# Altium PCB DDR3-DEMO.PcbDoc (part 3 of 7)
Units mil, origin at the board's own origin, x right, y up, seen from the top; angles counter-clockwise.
Board outline 2827 x 2165.35 mil, 8 copper layers (TOP, GND02, ART03, ART04, PWR05, ART06, GND07, BOTTOM); 111 components, 133 nets, 5542 pads, 873 vias.
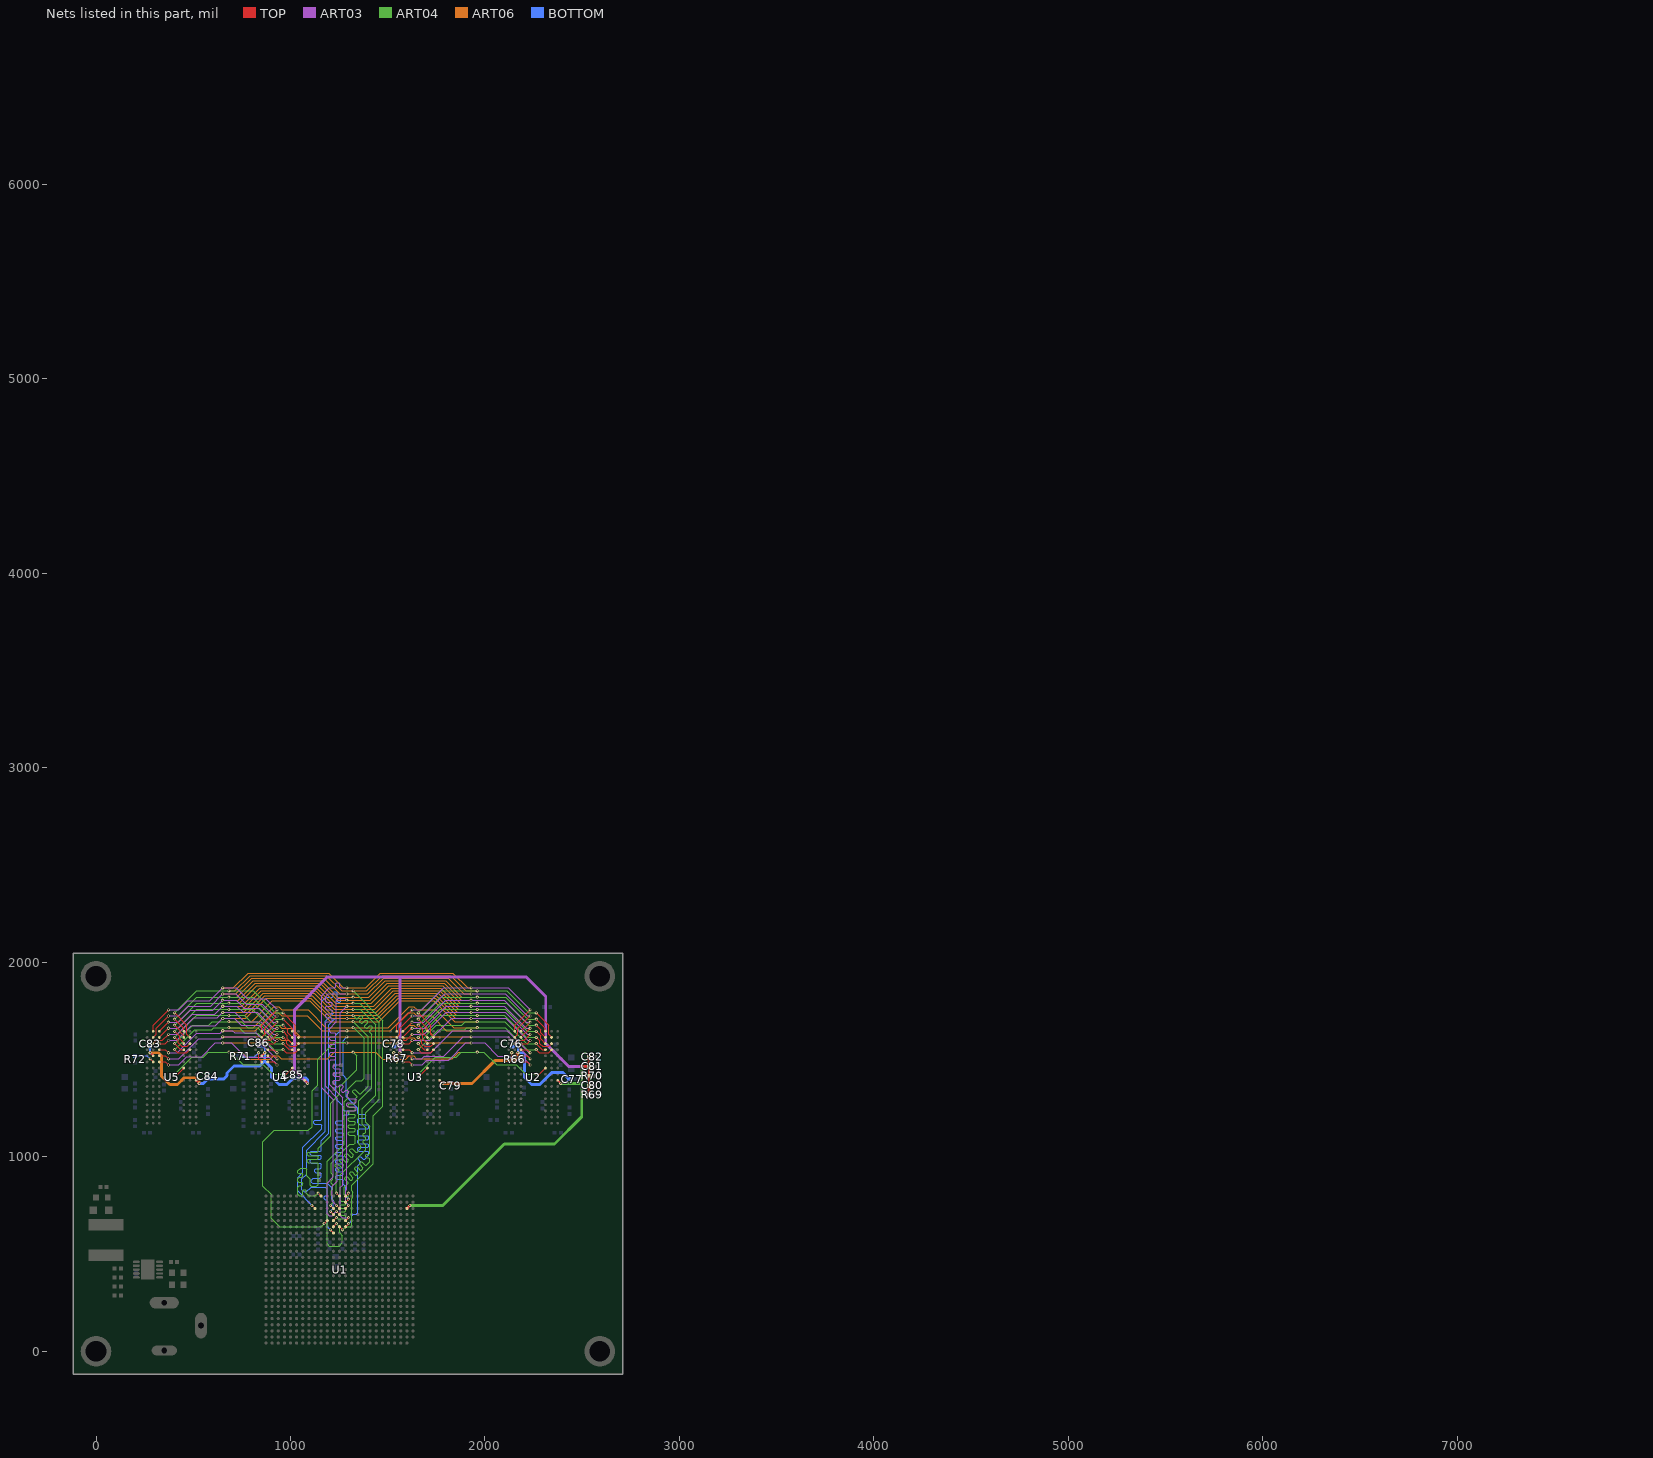
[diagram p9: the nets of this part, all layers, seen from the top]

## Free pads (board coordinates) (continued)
  round 8 on Drill Drawing: 1(4391.24,708.77) 1(4391.24,708.77) 1(4391.24,783.77) 1(4391.24,783.77) 1(4409.9,708.77) 1(4409.9,708.77) 1(4409.9,783.77) 1(4409.9,783.77) 1(4417.37,712.52) 1(4417.37,712.52) 1(4417.37,780.02) 1(4417.37,780.02) 1(4422.97,717.52) 1(4422.97,717.52) 1(4422.97,775.02) 1(4422.97,775.02) 1(4427.64,725.02) 1(4427.64,725.02) 1(4427.64,767.52) 1(4427.64,767.52) 1(4431.37,733.77) 1(4431.37,733.77) 1(4431.37,758.77) 1(4431.37,758.77) 1(4432.3,746.27) 1(4432.3,746.27) 1(4475.58,708.77) 1(4475.58,783.77) 1(4486.78,708.77) 1(4486.78,783.77) 1(4497.97,708.77) 1(4497.97,783.77) 1(4544.05,708.77) 1(4544.05,747.52) 1(4544.05,783.77) 1(4544.05,783.77) 1(4566.45,747.52) 1(4579.51,783.77) 1(4593.44,1542.62) 1(4597.17,1588.88) 1(4597.17,1588.88) 1(4599.04,1597.63) 1(4599.04,1597.63) 1(4599.97,1580.12) 1(4599.97,1580.12) 1(4600.91,1536.38) 1(4600.91,1536.38) 1(4603.71,1603.88) 1(4603.71,1603.88) 1(4606.51,1575.12) 1(4606.51,1575.12) 1(4609.31,1532.62) 1(4609.31,1532.62) 1(4610.24,1607.63) 1(4610.24,1607.63) 1(4616.77,1532.62) 1(4616.77,1532.62) 1(4616.77,1607.63) 1(4616.77,1607.63) 1(4617.71,1572.62) 1(4617.71,1572.62) 1(4619.05,708.77) 1(4619.05,747.52) 1(4619.05,783.77) 1(4619.05,783.77) 1(4623.31,1605.13) 1(4623.31,1605.13) 1(4624.24,1536.38) 1(4624.24,1536.38) 1(4626.11,1567.62) 1(4626.11,1567.62) 1(4628.91,1598.88) 1(4629.84,1542.62) 1(4629.84,1542.62) 1(4630.77,1560.12) 1(4630.77,1560.12) 1(4632.64,1551.38) 1(4632.64,1551.38) 1(4641.45,747.52) 1(4654.51,783.77) 1(4676.84,1532.62) 1(4676.84,1607.63) 1(4688.04,1532.62) 1(4688.04,1607.63) 1(4693.11,708.77) 1(4693.11,708.77) 1(4693.11,747.52) 1(4693.11,783.77) 1(4693.11,783.77) 1(4699.24,1532.62) 1(4699.24,1607.63) 1(4715.51,747.52) 1(4730.45,708.77) 1(4730.45,783.77) 1(4741.57,1532.62) 1(4741.57,1607.63) 1(4741.57,1607.63) 1(4768.11,708.77) 1(4768.11,745.02) 1(4768.11,783.77) 1(4768.11,783.77) 1(4784.51,1532.62) 1(4784.51,1532.62) 1(4784.51,1607.63) 1(4791.45,745.02) 1(4791.45,745.02) 1(4791.45,745.02) 1(4791.45,783.77) 1(4791.45,783.77) 1(4797.98,748.77) 1(4797.98,748.77) 1(4798.91,780.02) 1(4798.91,780.02) 1(4803.58,755.02) 1(4803.58,755.02) 1(4803.58,775.02) 1(4803.58,775.02) 1(4805.45,708.77) 1(4805.45,765.02) 1(4805.45,765.02) 1(4813.77,1566.38) 1(4813.77,1566.38) 1(4813.77,1575.12) 1(4813.77,1575.12) 1(4815.64,1556.38) 1(4815.64,1556.38) 1(4815.64,1582.62) 1(4815.64,1582.62) 1(4819.37,1547.62) 1(4819.37,1547.62) 1(4819.37,1591.38) 1(4819.37,1591.38) 1(4824.97,1540.12) 1(4824.97,1540.12) 1(4824.97,1598.88) 1(4824.97,1598.88) 1(4830.57,1603.88) 1(4830.57,1603.88) 1(4831.51,1535.12) 1(4831.51,1535.12) 1(4838.04,1607.63) 1(4838.04,1607.63) 1(4840.84,1532.62) 1(4840.84,1532.62) 1(4843.11,708.77) 1(4843.11,708.77) 1(4843.11,747.52) 1(4843.11,783.77) 1(4843.11,783.77) 1(4843.64,1570.12) 1(4844.57,1607.63) 1(4844.57,1607.63) 1(4850.17,1535.12) 1(4850.17,1535.12) 1(4852.04,1605.13) 1(4852.04,1605.13) 1(4856.71,1540.12) 1(4856.71,1540.12) 1(4857.64,1600.13) 1(4862.31,1547.62) 1(4862.31,1547.62) 1(4862.31,1570.12) 1(4862.31,1570.12) 1(4865.51,747.52) 1(4880.45,708.77) 1(4880.45,783.77) 1(4894.37,1532.62) 1(4894.37,1532.62) 1(4894.37,1607.63) 1(4915.31,708.77) 1(4915.31,783.77) 1(4915.31,783.77) 1(4931.71,1532.62) 1(4958.25,708.77) 1(4958.25,708.77) 1(4958.25,783.77) 1(4969.37,1532.62) 1(4969.37,1532.62) 1(4969.37,1571.38) 1(4969.37,1607.63) 1(4969.37,1607.63) 1(4990.31,783.77) 1(4991.77,1571.38) 1(5006.71,1532.62) 1(5006.71,1607.63) 1(5011.78,708.77) 1(5011.78,783.77) 1(5033.25,783.77) 1(5075.58,783.77) 1(5086.78,708.77) 1(5086.78,783.77) 1(5097.98,783.77) 1(5116.57,1607.63) 1(5137.39,696.56) 1(5138.04,1532.62) 1(5138.04,1607.63) 1(5138.45,708.77) 1(5146.85,735.02) 1(5159.51,1607.63) 1(5159.79,696.56) 1(5161.78,783.77) 1(5161.78,783.77) 1(5176.71,735.02) 1(5185.11,708.77) 1(5194.37,1532.62) 1(5194.37,1568.88) 1(5194.37,1607.63) 1(5194.37,1607.63) 1(5217.71,1568.88) 1(5217.71,1568.88) 1(5217.71,1568.88) 1(5217.71,1607.63) 1(5217.71,1607.63) 1(5218.11,708.77) 1(5218.11,708.77) 1(5218.11,783.77) 1(5224.24,1572.62) 1(5224.24,1572.62) 1(5225.17,1603.88) 1(5225.17,1603.88) 1(5229.84,1578.88) 1(5229.84,1578.88) 1(5229.84,1598.88) 1(5229.84,1598.88) 1(5231.71,1532.62) 1(5231.71,1588.88) 1(5231.71,1588.88) 1(5255.45,708.77) 1(5264.71,1532.62) 1(5273.11,1558.88) 1(5288.04,1607.63) 1(5288.04,1607.63) 1(5302.97,1558.88) 1(5311.37,1532.62) 1(5339.71,1566.38) 1(5339.71,1566.38) 1(5340.64,1577.62) 1(5340.64,1577.62) 1(5341.57,1555.12) 1(5341.57,1555.12) 1(5344.37,1547.62) 1(5344.37,1547.62) 1(5344.37,1590.13) 1(5344.37,1590.13) 1(5349.04,1597.63) 1(5349.04,1597.63) 1(5349.97,1540.12) 1(5349.97,1540.12) 1(5355.57,1603.88) 1(5355.57,1603.88) 1(5356.51,1535.12) 1(5356.51,1535.12) 1(5363.04,1532.62) 1(5363.04,1532.62) 1(5363.97,1607.63) 1(5363.97,1607.63) 1(5365.31,783.77) 1(5369.57,1532.62) 1(5369.57,1532.62) 1(5371.44,1607.63) 1(5371.44,1607.63) 1(5376.11,1535.12) 1(5376.11,1535.12) 1(5377.97,1605.13) 1(5377.97,1605.13) 1(5381.71,1538.88) 1(5381.71,1538.88) 1(5383.57,1601.38) 1(5386.37,1543.88) 1(5386.78,708.77) 1(5386.78,783.77) 1(5408.25,783.77) 1(5419.37,1532.62) 1(5419.37,1532.62) 1(5419.37,1571.38) 1(5419.37,1607.63) 1(5419.37,1607.63) 1(5441.77,1571.38) 1(5443.11,708.77) 1(5443.11,745.02) 1(5443.11,783.77) 1(5443.11,783.77) 1(5456.71,1532.62) 1(5456.71,1607.63) 1(5466.45,745.02) 1(5466.45,745.02) 1(5466.45,745.02) 1(5466.45,783.77) 1(5466.45,783.77) 1(5472.98,748.77) 1(5472.98,748.77) 1(5473.91,780.02) 1(5473.91,780.02) 1(5478.58,755.02) 1(5478.58,755.02) 1(5478.58,775.02) 1(5478.58,775.02) 1(5480.45,708.77) 1(5480.45,765.02) 1(5480.45,765.02) 1(5513.45,708.77) 1(5521.85,735.02) 1(5536.78,783.77) 1(5536.78,783.77) 1(5551.71,735.02) 1(5560.11,708.77) 1(5576.84,1532.62) 1(5576.84,1607.63) 1(5588.04,1532.62) 1(5588.04,1607.63) 1(5588.45,742.52) 1(5588.45,742.52) 1(5589.38,753.77) 1(5589.38,753.77) 1(5590.31,731.27) 1(5590.31,731.27) 1(5593.11,723.77) 1(5593.11,723.77) 1(5593.11,766.27) 1(5593.11,766.27) 1(5597.78,773.77) 1(5597.78,773.77) 1(5598.71,716.27) 1(5598.71,716.27) 1(5599.24,1532.62) 1(5599.24,1607.63) 1(5604.31,780.02) 1(5604.31,780.02) 1(5605.25,711.27) 1(5605.25,711.27) 1(5611.78,708.77) 1(5611.78,708.77) 1(5612.71,783.77) 1(5612.71,783.77) 1(5618.31,708.77) 1(5618.31,708.77) 1(5620.18,783.77) 1(5620.18,783.77) 1(5624.85,711.27) 1(5624.85,711.27) 1(5626.71,781.27) 1(5626.71,781.27) 1(5630.45,715.02) 1(5630.45,715.02) 1(5632.31,777.52) 1(5635.11,720.02) 1(5638.77,1532.62) 1(5638.77,1607.63) 1(5638.77,1607.63) 1(5663.04,1545.12) 1(5663.04,1545.12) 1(5668.11,708.77) 1(5668.11,708.77) 1(5668.11,747.52) 1(5668.11,783.77) 1(5668.11,783.77) 1(5687.31,1532.62) 1(5687.31,1607.63) 1(5687.31,1607.63) 1(5690.51,747.52) 1(5705.45,708.77) 1(5705.45,783.77) 1(5719.37,1532.62) 1(5719.37,1563.88) 1(5719.37,1607.63) 1(5719.37,1607.63) 1(5741.77,1563.88) 1(5741.77,1563.88) 1(5741.77,1607.63) 1(5741.77,1607.63) 1(5749.24,1603.88) 1(5749.24,1603.88) 1(5750.17,1567.62) 1(5750.17,1567.62) 1(5754.84,1575.12) 1(5754.84,1575.12) 1(5754.84,1595.13) 1(5754.84,1595.13) 1(5756.71,1585.12) 1(5756.71,1585.12) 1(5794.37,1532.62) 1(5794.37,1532.62) 1(5794.37,1571.38) 1(5794.37,1607.63) 1(5794.37,1607.63) 1(5816.77,1571.38) 1(5825.58,708.77) 1(5825.58,783.77) 1(5831.71,1532.62) 1(5831.71,1607.63) 1(5836.78,708.77) 1(5836.78,783.77) 1(5847.98,708.77) 1(5847.98,783.77) 1(5867.51,1532.62) 1(5867.51,1532.62) 1(5867.51,1607.63) 1(5867.51,1607.63) 1(5886.17,1532.62) 1(5886.17,1532.62) 1(5886.17,1607.63) 1(5886.17,1607.63) 1(5887.51,708.77) 1(5887.51,783.77) 1(5887.51,783.77) 1(5893.64,1536.38) 1(5893.64,1536.38) 1(5893.64,1603.88) 1(5893.64,1603.88) 1(5899.24,1541.38) 1(5899.24,1541.38) 1(5899.24,1598.88) 1(5899.24,1598.88) 1(5903.91,1548.88) 1(5903.91,1548.88) 1(5903.91,1591.38) 1(5903.91,1591.38) 1(5907.64,1557.62) 1(5907.64,1557.62) 1(5907.64,1582.62) 1(5907.64,1582.62) 1(5908.57,1570.12) 1(5908.57,1570.12) 1(5911.78,721.27) 1(5911.78,721.27) 1(5936.05,708.77) 1(5936.05,783.77) 1(5936.05,783.77) 1(5939.71,1532.62) 1(5948.11,1558.88) 1(5963.04,1607.63) 1(5963.04,1607.63) 1(5968.11,708.77) 1(5968.11,740.02) 1(5968.11,783.77) 1(5968.11,783.77) 1(5977.97,1558.88) 1(5986.37,1532.62) 1(5990.51,740.02) 1(5990.51,740.02) 1(5990.51,783.77) 1(5990.51,783.77) 1(5997.98,780.02) 1(5997.98,780.02) 1(5998.91,743.77) 1(5998.91,743.77) 1(6003.58,751.27) 1(6003.58,751.27) 1(6003.58,771.27) 1(6003.58,771.27) 1(6005.45,761.27) 1(6005.45,761.27) 1(6016.57,1532.62) 1(6016.57,1607.63) 1(6016.57,1607.63) 1(6043.11,708.77) 1(6043.11,708.77) 1(6043.11,747.52) 1(6043.11,783.77) 1(6043.11,783.77) 1(6059.51,1532.62) 1(6059.51,1532.62) 1(6059.51,1607.63) 1(6065.51,747.52) 1(6080.45,708.77) 1(6080.45,783.77) 1(6089.71,1566.38) 1(6089.71,1566.38) 1(6090.64,1577.62) 1(6090.64,1577.62) 1(6091.57,1555.12) 1(6091.57,1555.12) 1(6094.37,1547.62) 1(6094.37,1547.62) 1(6094.37,1590.13) 1(6094.37,1590.13) 1(6099.04,1597.63) 1(6099.04,1597.63) 1(6099.97,1540.12) 1(6099.97,1540.12) 1(6105.57,1603.88) 1(6105.57,1603.88) 1(6106.51,1535.12) 1(6106.51,1535.12) 1(6113.04,1532.62) 1(6113.04,1532.62) 1(6113.97,1607.63) 1(6113.97,1607.63) 1(6116.25,708.77) 1(6116.25,708.77) 1(6116.25,783.77) 1(6116.25,783.77) 1(6119.57,1532.62) 1(6119.57,1532.62) 1(6121.44,1607.63) 1(6121.44,1607.63) 1(6126.11,1535.12) 1(6126.11,1535.12) 1(6127.97,1605.13) 1(6127.97,1605.13) 1(6131.71,1538.88) 1(6131.71,1538.88) 1(6133.57,1601.38) 1(6134.91,708.77) 1(6134.91,708.77) 1(6134.91,783.77) 1(6134.91,783.77) 1(6136.37,1543.88) 1(6142.38,712.52) 1(6142.38,712.52) 1(6142.38,780.02) 1(6142.38,780.02) 1(6147.98,717.52) 1(6147.98,717.52) 1(6147.98,775.02) 1(6147.98,775.02) 1(6152.65,725.02) 1(6152.65,725.02) 1(6152.65,767.52) 1(6152.65,767.52) 1(6156.38,733.77) 1(6156.38,733.77) 1(6156.38,758.77) 1(6156.38,758.77) 1(6157.31,746.27) 1(6157.31,746.27) 1(6169.37,1532.62) 1(6169.37,1532.62) 1(6169.37,1571.38) 1(6169.37,1607.63) 1(6169.37,1607.63) 1(6188.45,708.77) 1(6191.77,1571.38) 1(6196.85,735.02) 1(6206.71,1532.62) 1(6206.71,1607.63) 1(6211.78,783.77) 1(6211.78,783.77) 1(6226.71,735.02) 1(6235.11,708.77) 1(6265.31,708.77) 1(6265.31,783.77) 1(6265.31,783.77) 1(6308.25,708.77) 1(6308.25,708.77) 1(6308.25,783.77) 1(6314.71,1566.38) 1(6314.71,1566.38) 1(6315.64,1577.62) 1(6315.64,1577.62) 1(6316.57,1555.12) 1(6316.57,1555.12) 1(6319.37,1547.62) 1(6319.37,1547.62) 1(6319.37,1590.13) 1(6319.37,1590.13) 1(6324.04,1597.63) 1(6324.04,1597.63) 1(6324.97,1540.12) 1(6324.97,1540.12) 1(6330.57,1603.88) 1(6330.57,1603.88) 1(6331.51,1535.12) 1(6331.51,1535.12) 1(6338.04,1532.62) 1(6338.04,1532.62) 1(6338.45,742.52) 1(6338.45,742.52) 1(6338.97,1607.63) 1(6338.97,1607.63) 1(6339.38,753.77) 1(6339.38,753.77) 1(6340.31,731.27) 1(6340.31,731.27) 1(6343.11,723.77) 1(6343.11,723.77) 1(6343.11,766.27) 1(6343.11,766.27) 1(6344.57,1532.62) 1(6344.57,1532.62) 1(6346.44,1607.63) 1(6346.44,1607.63) 1(6347.78,773.77) 1(6347.78,773.77) 1(6348.71,716.27) 1(6348.71,716.27) 1(6351.11,1535.12) 1(6351.11,1535.12) 1(6352.97,1605.13) 1(6352.97,1605.13) 1(6354.31,780.02) 1(6354.31,780.02) 1(6355.25,711.27) 1(6355.25,711.27) 1(6356.71,1538.88) 1(6356.71,1538.88) 1(6358.57,1601.38) 1(6361.37,1543.88) 1(6361.78,708.77) 1(6361.78,708.77) 1(6362.71,783.77) 1(6362.71,783.77) 1(6368.31,708.77) 1(6368.31,708.77) 1(6370.18,783.77) 1(6370.18,783.77) 1(6374.85,711.27) 1(6374.85,711.27) 1(6376.71,781.27) 1(6376.71,781.27) 1(6380.45,715.02) 1(6380.45,715.02) 1(6382.31,777.52) 1(6385.11,720.02) 1(6387.84,1565.12) 1(6387.84,1565.12) 1(6387.84,1575.12) 1(6387.84,1575.12) 1(6389.71,1555.12) 1(6389.71,1555.12) 1(6389.71,1585.12) 1(6389.71,1585.12) 1(6393.44,1546.38) 1(6393.44,1546.38) 1(6393.44,1593.88) 1(6393.44,1593.88) 1(6399.04,1538.88) 1(6399.04,1538.88) 1(6399.04,1601.38) 1(6399.04,1601.38) 1(6405.57,1533.88) 1(6405.57,1533.88) 1(6405.57,1606.38) 1(6405.57,1606.38) 1(6413.04,1532.62) 1(6413.04,1532.62) 1(6413.04,1607.63) 1(6413.04,1607.63) 1(6418.11,708.77) 1(6418.11,708.77) 1(6418.11,747.52) 1(6418.11,783.77) 1(6418.11,783.77) 1(6420.51,1533.88) 1(6420.51,1533.88) 1(6420.51,1606.38) 1(6420.51,1606.38) 1(6427.04,1538.88) 1(6427.04,1538.88) 1(6427.04,1601.38) 1(6427.04,1601.38) 1(6432.64,1546.38) 1(6432.64,1546.38) 1(6432.64,1593.88) 1(6432.64,1593.88) 1(6436.37,1555.12) 1(6436.37,1555.12) 1(6436.37,1585.12) 1(6436.37,1585.12) 1(6438.24,1565.12) 1(6438.24,1565.12) 1(6438.24,1575.12) 1(6438.24,1575.12) 1(6440.51,747.52) 1(6455.45,708.77) 1(6455.45,783.77) 1(6466.57,1532.62) 1(6466.57,1607.63) 1(6466.57,1607.63) 1(6509.51,1532.62) 1(6509.51,1532.62) 1(6509.51,1607.63) 1(6541.57,1607.63) 1(6563.04,1532.62) 1(6563.04,1607.63) 1(6563.45,742.52) 1(6563.45,742.52) 1(6564.38,753.77) 1(6564.38,753.77) 1(6565.31,731.27) 1(6565.31,731.27) 1(6568.11,723.77) 1(6568.11,723.77) 1(6568.11,766.27) 1(6568.11,766.27) 1(6572.78,773.77) 1(6572.78,773.77) 1(6573.71,716.27) 1(6573.71,716.27) 1(6579.31,780.02) 1(6579.31,780.02) 1(6580.25,711.27) 1(6580.25,711.27) 1(6584.51,1607.63) 1(6586.78,708.77) 1(6586.78,708.77) 1(6587.71,783.77) 1(6587.71,783.77) 1(6593.31,708.77) 1(6593.31,708.77) 1(6595.18,783.77) 1(6595.18,783.77) 1(6599.85,711.27) 1(6599.85,711.27) 1(6601.71,781.27) 1(6601.71,781.27) 1(6605.45,715.02) 1(6605.45,715.02) 1(6607.31,777.52) 1(6610.11,720.02) 1(6619.37,1532.62) 1(6619.37,1568.88) 1(6619.37,1607.63) 1(6619.37,1607.63) 1(6636.58,741.27) 1(6636.58,741.27) 1(6636.58,751.27) 1(6636.58,751.27) 1(6638.45,731.27) 1(6638.45,731.27) 1(6638.45,761.27) 1(6638.45,761.27) 1(6642.18,722.52) 1(6642.18,722.52) 1(6642.18,770.02) 1(6642.18,770.02) 1(6642.71,1568.88) 1(6642.71,1568.88) 1(6642.71,1568.88) 1(6642.71,1607.63) 1(6642.71,1607.63) 1(6647.78,715.02) 1(6647.78,715.02) 1(6647.78,777.52) 1(6647.78,777.52) 1(6649.24,1572.62) 1(6649.24,1572.62) 1(6650.17,1603.88) 1(6650.17,1603.88) 1(6654.31,710.02) 1(6654.31,710.02) 1(6654.31,782.52) 1(6654.31,782.52) 1(6654.84,1578.88) 1(6654.84,1578.88) 1(6654.84,1598.88) 1(6654.84,1598.88) 1(6656.71,1532.62) 1(6656.71,1588.88) 1(6656.71,1588.88) 1(6661.78,708.77) 1(6661.78,708.77) 1(6661.78,783.77) 1(6661.78,783.77) 1(6669.25,710.02) 1(6669.25,710.02) 1(6669.25,782.52) 1(6669.25,782.52) 1(6675.78,715.02) 1(6675.78,715.02) 1(6675.78,777.52) 1(6675.78,777.52) 1(6681.38,722.52) 1(6681.38,722.52) 1(6681.38,770.02) 1(6681.38,770.02) 1(6685.11,731.27) 1(6685.11,731.27) 1(6685.11,761.27) 1(6685.11,761.27) 1(6686.98,741.27) 1(6686.98,741.27) 1(6686.98,751.27) 1(6686.98,751.27) 1(6687.84,1565.12) 1(6687.84,1565.12) 1(6687.84,1575.12) 1(6687.84,1575.12) 1(6689.71,1555.12) 1(6689.71,1555.12) 1(6689.71,1585.12) 1(6689.71,1585.12) 1(6693.44,1546.38) 1(6693.44,1546.38) 1(6693.44,1593.88) 1(6693.44,1593.88) 1(6699.04,1538.88) 1(6699.04,1538.88) 1(6699.04,1601.38) 1(6699.04,1601.38) 1(6705.57,1533.88) 1(6705.57,1533.88) 1(6705.57,1606.38) 1(6705.57,1606.38) 1(6713.04,1532.62) 1(6713.04,1532.62) 1(6713.04,1607.63) 1(6713.04,1607.63) 1(6715.31,708.77) 1(6715.31,783.77) 1(6715.31,783.77) 1(6720.51,1533.88) 1(6720.51,1533.88) 1(6720.51,1606.38) 1(6720.51,1606.38) 1(6727.04,1538.88) 1(6727.04,1538.88) 1(6727.04,1601.38) 1(6727.04,1601.38) 1(6732.64,1546.38) 1(6732.64,1546.38) 1(6732.64,1593.88) 1(6732.64,1593.88) 1(6736.37,1555.12) 1(6736.37,1555.12) 1(6736.37,1585.12) 1(6736.37,1585.12) 1(6738.24,1565.12) 1(6738.24,1565.12) 1(6738.24,1575.12) 1(6738.24,1575.12) 1(6758.25,708.77) 1(6758.25,708.77) 1(6758.25,783.77) 1(6769.37,1532.62) 1(6769.37,1532.62) 1(6769.37,1607.63) 1(6790.31,783.77) 1(6806.71,1532.62) 1(6811.78,708.77) 1(6811.78,783.77) 1(6833.25,783.77) 1(6868.11,708.77) 1(6868.11,745.02) 1(6868.11,783.77) 1(6868.11,783.77) 1(6891.45,745.02) 1(6891.45,745.02) 1(6891.45,745.02) 1(6891.45,783.77) 1(6891.45,783.77) 1(6897.98,748.77) 1(6897.98,748.77) 1(6898.91,780.02) 1(6898.91,780.02) 1(6903.58,755.02) 1(6903.58,755.02) 1(6903.58,775.02) 1(6903.58,775.02) 1(6905.45,708.77) 1(6905.45,765.02) 1(6905.45,765.02) 1(6936.58,741.27) 1(6936.58,741.27) 1(6936.58,751.27) 1(6936.58,751.27) 1(6938.45,731.27) 1(6938.45,731.27) 1(6938.45,761.27) 1(6938.45,761.27) 1(6942.18,722.52) 1(6942.18,722.52) 1(6942.18,770.02) 1(6942.18,770.02) 1(6947.78,715.02) 1(6947.78,715.02) 1(6947.78,777.52) 1(6947.78,777.52) 1(6954.31,710.02) 1(6954.31,710.02) 1(6954.31,782.52) 1(6954.31,782.52) 1(6961.78,708.77) 1(6961.78,708.77) 1(6961.78,783.77) 1(6961.78,783.77) 1(6969.25,710.02) 1(6969.25,710.02) 1(6969.25,782.52) 1(6969.25,782.52) 1(6975.78,715.02) 1(6975.78,715.02) 1(6975.78,777.52) 1(6975.78,777.52) 1(6981.38,722.52) 1(6981.38,722.52) 1(6981.38,770.02) 1(6981.38,770.02) 1(6985.11,731.27) 1(6985.11,731.27) 1(6985.11,761.27) 1(6985.11,761.27) 1(6986.98,741.27) 1(6986.98,741.27) 1(6986.98,751.27) 1(6986.98,751.27) 1(7018.11,708.77) 1(7018.11,708.77) 1(7018.11,783.77) 1(7055.45,708.77)
  round 11.8 on Drill Drawing: 1(4483.38,4813.17) 1(4483.38,4813.17) 1(4483.38,4902.93) 1(4483.38,4902.93) 1(4483.38,5763.17) 1(4483.38,5763.17) 1(4483.38,5852.93) 1(4483.38,5852.93) 1(4484.16,5913.95) 1(4484.16,5913.95) 1(4484.16,6003.71) 1(4484.16,6003.71) 1(4484.16,5413.95) 1(4484.16,5413.95) 1(4484.16,5503.71) 1(4484.16,5503.71) 1(4573.14,4813.17) 1(4573.14,4813.17) 1(4573.14,4902.93) 1(4573.14,4902.93) 1(4573.14,5763.17) 1(4573.14,5763.17) 1(4573.14,5852.93) 1(4573.14,5852.93) 1(4573.92,5913.95) 1(4573.92,5913.95) 1(4573.92,6003.71) 1(4573.92,6003.71) 1(4573.92,5413.95) 1(4573.92,5413.95) 1(4573.92,5503.71) 1(4573.92,5503.71) 1(5158.58,5113.17) 1(5158.58,5113.17) 1(5158.58,5202.93) 1(5158.58,5202.93) 1(5248.34,5113.17) 1(5248.34,5113.17) 1(5248.34,5202.93) 1(5248.34,5202.93) 1(5784.28,6364.44) 1(5784.28,6364.44) 1(5784.28,6454.2) 1(5784.28,6454.2) 1(5874.04,6364.44) 1(5874.04,6364.44) 1(5874.04,6454.2) 1(5874.04,6454.2) 1(6159.36,5263.95) 1(6159.36,5263.95) 1(6159.36,5353.71) 1(6159.36,5353.71) 1(6249.12,5263.95) 1(6249.12,5263.95) 1(6249.12,5353.71) 1(6249.12,5353.71) 1(7245.19,6060.02) 1(7245.19,6060.02) 1(7245.19,6149.78) 1(7245.19,6149.78) 1(7334.95,6060.02) 1(7334.95,6060.02) 1(7334.95,6149.78) 1(7334.95,6149.78)

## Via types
v1: diameter 16, hole 8, TOP to BOTTOM, tented both sides, 873 vias

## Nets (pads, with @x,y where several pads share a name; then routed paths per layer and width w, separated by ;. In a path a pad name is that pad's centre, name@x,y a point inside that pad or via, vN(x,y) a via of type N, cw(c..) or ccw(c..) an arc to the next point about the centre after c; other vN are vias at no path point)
DDR_VREF: C76.1 C77.1 C78.1 C79.1 C80.2 C81.1 C82.1 C83.1 C84.1 C85.1 C86.1 R69.2 R70.1 U1.AC2 U2.H1 U2.M8 U3.H1 U3.M8 U4.H1 U4.M8 U5.H1 U5.M8 | length 6939.1
  TOP w10: v1(278.16,1535.12) U5.M8@293.91,1519.37 ; U5.H1@514.38,1393.38 v1(530.13,1377.63) ; U4.M8@851.89,1519.37 v1(867.64,1535.12) ; U4.H1@1072.36,1393.38 v1(1088.11,1377.63) ; U3.M8@1546.41,1519.37 v1(1562.16,1535.12) ; U3.H1@1766.88,1393.38 v1(1782.63,1377.63) ; U2.M8@2153.42,1519.37 v1(2169.17,1535.12) ; U2.H1@2373.89,1393.38 v1(2389.64,1377.63) ; C80.2@2534.42,1367.35 R70.1@2534.42,1416.35 C81.1@2534.42,1465.35
  TOP w12: U1.AC2@1598.36,734.86 v1(1614.11,750.61)
  TOP w15: v1(2497.42,1465.35) C81.1@2534.42,1465.35 C82.1@2534.42,1514.35 ; R69.2@2534.42,1318.35 C80.2@2534.42,1367.35
  ART03 w15: v1(1088.11,1377.63) 1021.42,1444.32 1021.42,1756.35 1190.42,1925.35 2211.42,1925.35 2312.42,1824.35 2312.42,1582.35 2429.42,1465.35 v1(2497.42,1465.35) ; v1(1562.16,1535.12) 1562.16,1923.61
  ART04 w10: 2493.7,1377.63 2497.42,1381.35
  ART04 w15: v1(1614.11,750.61) 1783.68,750.61 2099.42,1066.35 2357.42,1066.35 2497.42,1206.35 2497.42,1381.35 v1(2497.42,1465.35) ; v1(2389.64,1377.63) 2493.7,1377.63
  ART06 w15: v1(278.16,1535.12) 321.65,1535.12 336.42,1520.35 336.42,1414.35 379.42,1371.35 418.42,1371.35 453.42,1406.35 518.42,1406.35 530.13,1394.64 v1(530.13,1377.63) ; v1(1782.63,1377.63) 1933.7,1377.63 2050.42,1494.35 2148.42,1494.35 2169.17,1515.1 v1(2169.17,1535.12)
  BOTTOM w10: v1(278.16,1535.12) 278.42,1535.38 C83.1@278.42,1566.35 ; C86.1@836.4,1566.35 858.42,1566.35 867.64,1557.13 v1(867.64,1535.12) ; C78.1@1530.92,1566.35 1554.42,1566.35 1562.16,1558.61 v1(1562.16,1535.12) ; v1(1782.63,1377.63) 1821.13,1377.63 C79.1@1824.42,1380.92 ; C76.1@2137.93,1566.35 2162.42,1566.35 2169.17,1559.6 v1(2169.17,1535.12) ; v1(2389.64,1377.63) 2411.21,1377.63 C77.1@2432.93,1399.35
  BOTTOM w14: 902.42,1409.35 940.42,1371.35
  BOTTOM w15: v1(530.13,1377.63) 551.7,1377.63 C84.1@573.42,1399.35 655.42,1399.35 673.42,1417.35 673.42,1430.35 709.42,1466.35 841.42,1466.35 867.64,1492.57 ; v1(867.64,1535.12) 867.64,1492.57 ; 902.42,1409.35 902.42,1457.79 867.64,1492.57 ; 940.42,1371.35 980.42,1371.35 C85.1@1014.42,1405.35 1078.42,1405.35 1088.11,1395.66 v1(1088.11,1377.63) ; v1(2169.17,1535.12) 2189.65,1535.12 2202.42,1522.35 2202.42,1407.35 2238.42,1371.35 2281.42,1371.35 2344.42,1434.35 2397.93,1434.35 C77.1@2432.93,1399.35
DRAM0_ZQ: R66.2 U2.L8 | length 86.6
  TOP w6: v1(2137.67,1535.12) 2137.67,1503.62 U2.L8@2153.42,1487.87
  BOTTOM w6: R66.2@2137.42,1502.35 2137.42,1534.87 v1(2137.67,1535.12)
DRAM1_ZQ: R67.2 U3.L8 | length 81.6
  TOP w6: v1(1530.66,1535.12) 1530.66,1503.62 U3.L8@1546.41,1487.87
  BOTTOM w6: R67.2@1530.42,1507.35 1530.42,1534.88 v1(1530.66,1535.12)
DRAM2_ZQ: R71.2 U4.L8 | length 140.8
  TOP w6: v1(836.14,1535.12) 836.14,1503.62 U4.L8@851.89,1487.87
  BOTTOM w6: R71.2@759.42,1516.35 762.42,1513.35 814.37,1513.35 v1(836.14,1535.12)
DRAM3_ZQ: R72.2 U5.L8 | length 107.3
  TOP w6: v1(278.16,1503.62) U5.L8@293.91,1487.87
  BOTTOM w6: R72.2@201.28,1517.35 204.28,1520.35 261.43,1520.35 v1(278.16,1503.62)
DRAM_A0: U1.AC14 U2.N3 U3.N3 U4.N3 U5.N3 | length 4533.3
  TOP w6: v1(404.15,1582.35) 435.64,1550.86 U5.N3@451.39,1550.86 ; v1(962.13,1582.35) 993.62,1550.86 U4.N3@1009.37,1550.86 ; v1(1204.65,750.61) U1.AC14@1220.4,734.86 ; v1(1656.65,1582.35) 1688.14,1550.86 U3.N3@1703.89,1550.86 ; v1(2263.66,1582.35) 2295.15,1550.86 U2.N3@2310.9,1550.86
  ART04 w6: v1(404.15,1582.35) 498.15,1676.35 578.89,1676.35 598,1695.46 v1(683.14,1695.46) 748.31,1695.46 779.42,1664.35 830.89,1664.35 912.89,1582.35 v1(962.13,1582.35) ; v1(1204.65,750.61) 1218.42,764.37 1218.42,793.35 1209.42,802.35 1209.42,826.35 1217.42,834.35 1217.42,855.35 1209.42,863.35 1209.42,876.35 1217.42,884.35 1217.42,907.35 1209.42,915.35 1209.42,967.35 1305.42,1063.35 1326.42,1063.35 1332.42,1069.35 1332.42,1106.85 1327.92,1111.35 1300.92,1111.35 1296.42,1115.85 1296.42,1124.85 1300.92,1129.35 1327.92,1129.35 1332.42,1133.85 1332.42,1142.85 1327.92,1147.35 1300.92,1147.35 1296.42,1151.85 1296.42,1160.85 1300.92,1165.35 1327.92,1165.35 1332.42,1169.85 1332.42,1178.85 1327.92,1183.35 1300.92,1183.35 1296.42,1187.85 1296.42,1196.85 1300.92,1201.35 1327.92,1201.35 1332.42,1205.85 1332.42,1214.85 1327.92,1219.35 1300.92,1219.35 1296.42,1223.85 1296.42,1232.85 1300.92,1237.35 1327.92,1237.35 1332.42,1241.85 1332.42,1250.85 1327.92,1255.35 1300.92,1255.35 1296.42,1259.85 1296.42,1268.85 1300.92,1273.35 1327.92,1273.35 1332.42,1277.85 1332.42,1296.35 1341.6,1305.53 1341.6,1311.9 1321.1,1332.4 1321.1,1338.77 1327.46,1345.13 1333.82,1345.13 1354.33,1324.62 1360.69,1324.62 1399.42,1363.35 1399.42,1617.69 v1(1321.65,1695.46) ; v1(1656.65,1582.35) 1750.65,1676.35 1880.42,1676.35 1899.53,1695.46 v1(1960.15,1695.46) 2101.31,1695.46 2214.42,1582.35 v1(2263.66,1582.35)
  ART06 w4.1: v1(683.14,1695.46) 800.53,1695.46 907.34,1802.27 1098.99,1802.27 1205.8,1695.46 v1(1321.65,1695.46) 1454.53,1695.46 1561.34,1802.27 1737.5,1802.27 1844.31,1695.46 v1(1960.15,1695.46)
DRAM_A1: U1.AB14 U2.P7 U3.P7 U4.P7 U5.P7 | length 4512.5
  TOP w6: U5.P7@325.41,1582.36 356.91,1582.36 v1(372.65,1598.11) ; U4.P7@883.39,1582.36 914.89,1582.36 v1(930.63,1598.11) ; v1(1204.65,719.11) U1.AB14@1220.4,703.36 ; U3.P7@1577.91,1582.36 1609.41,1582.36 v1(1625.15,1598.11) ; U2.P7@2184.92,1582.36 2216.42,1582.36 v1(2232.16,1598.11)
  ART03 w6: v1(372.65,1598.11) 414.65,1598.11 489.89,1673.35 613.77,1673.35 v1(651.64,1711.22) 710.55,1711.22 745.42,1676.35 837.42,1676.35 915.66,1598.11 v1(930.63,1598.11) ; v1(1625.15,1598.11) 1716.18,1598.11 1829.29,1711.22 v1(1928.65,1711.22) 2107.55,1711.22 2220.66,1598.11 v1(2232.16,1598.11)
  ART06 w4.1: v1(651.64,1711.22) 770.29,1711.22 874.27,1815.2 1105.07,1815.2 1209.04,1711.22 v1(1290.15,1711.22) 1449.29,1711.22 1553.27,1815.2 1743.57,1815.2 1847.55,1711.22 v1(1928.65,1711.22)
  BOTTOM w6: v1(1204.65,719.11) 1220.4,734.85 1220.4,776.37 1212.42,784.35 1212.42,841.35 1189.42,864.35 1113.42,864.35 1107.42,870.35 1107.42,880.35 1116.42,889.35 1150.42,889.35 1157.42,896.35 1157.42,913.35 1152.42,918.35 1129.37,918.35 1124.37,923.35 1124.37,933.35 1129.37,938.35 1152.42,938.35 1157.42,943.35 1157.42,962.35 1152.42,967.35 1107.09,967.35 1102.09,972.35 1102.09,982.35 1107.09,987.35 1152.42,987.35 1157.42,992.35 1157.42,1002.35 1152.42,1007.35 1107.09,1007.35 1102.09,1012.35 1102.09,1022.35 1107.09,1027.35 1152.42,1027.35 1157.42,1032.35 1157.42,1082.35 1196.42,1121.35 1196.42,1678.35 1229.29,1711.22 v1(1290.15,1711.22)
DRAM_A2: U1.AA14 U2.P3 U3.P3 U4.P3 U5.P3 | length 4584.3
  TOP w6: v1(404.15,1645.34) 430.42,1619.07 430.42,1608.35 451.39,1587.38 U5.P3@451.39,1582.36 ; v1(962.13,1645.34) 984.4,1623.07 984.4,1607.33 U4.P3@1009.37,1582.36 U4.P3@1009.37,1588.4 ; U1.AA14@1220.4,671.87 v1(1236.15,687.62) ; v1(1656.65,1645.34) 1678.92,1623.07 1678.92,1607.33 U3.P3@1703.89,1582.36 ; v1(2263.66,1645.34) 2285.93,1623.07 2285.93,1607.33 U2.P3@2310.9,1582.36 2310.9,1589.87
  ART04 w6: v1(404.15,1645.34) 517.26,1758.45 v1(683.14,1758.45) 803.79,1758.45 916.9,1645.34 v1(962.13,1645.34) ; v1(1236.15,687.62) 1242.41,681.35 1279.15,681.35 1283.65,685.85 1283.65,694.85 1279.15,699.35 1260.92,699.35 1256.42,703.85 1256.42,712.85 1260.92,717.35 1279.39,717.35 1283.89,721.85 1283.89,730.85 1279.39,735.35 1260.92,735.35 1256.42,739.85 1256.42,748.85 1260.92,753.35 1280.94,753.35 1285.44,757.85 1285.44,766.85 1280.94,771.35 1260.92,771.35 1256.42,775.85 1256.42,907.35 1386.42,1037.35 1386.42,1063.85 1381.92,1068.35 1377.57,1068.35 1373.07,1072.85 1373.07,1081.85 1377.57,1086.35 1381.92,1086.35 1386.42,1090.85 1386.42,1099.85 1381.92,1104.35 1377.57,1104.35 1373.07,1108.85 1373.07,1117.85 1377.57,1122.35 1381.92,1122.35 1386.42,1126.85 1386.42,1149.35 1369.42,1166.35 1369.42,1246.35 1438.42,1315.35 1438.42,1679.35 1359.32,1758.45 v1(1321.65,1758.45) ; v1(1656.65,1645.34) 1769.76,1758.45 v1(1960.15,1758.45) 2105.32,1758.45 2218.43,1645.34 v1(2263.66,1645.34)
  ART06 w4.1: v1(683.14,1758.45) 753.52,1758.45 849.03,1853.96 1129.3,1853.96 1224.81,1758.45 v1(1321.65,1758.45) 1432.52,1758.45 1528.03,1853.96 1767.8,1853.96 1863.32,1758.45 v1(1960.15,1758.45)
DRAM_A3: U1.Y14 U2.N2 U3.N2 U4.N2 U5.N2 | length 4630.2
  TOP w6: v1(404.15,1550.86) 419.66,1535.35 467.38,1535.35 U5.N2@482.89,1550.86 ; v1(962.13,1550.86) 977.64,1535.35 1025.36,1535.35 U4.N2@1040.87,1550.86 ; U1.Y14@1220.4,640.37 v1(1236.15,656.12) ; v1(1656.65,1550.86) 1672.16,1535.35 1719.88,1535.35 U3.N2@1735.39,1550.86 ; v1(2263.66,1550.86) 2279.17,1535.35 2326.89,1535.35 U2.N2@2342.4,1550.86
  ART04 w6: v1(404.15,1550.86) 506.64,1653.35 594.27,1653.35 604.89,1663.97 v1(683.14,1663.97) 736.8,1663.97 765.42,1635.35 831.89,1635.35 916.38,1550.86 v1(962.13,1550.86) ; v1@1236.15,656.12 1251.9,640.37 1251.9,609.87 1267.21,594.56 1267.21,558.14 1250.42,541.35 1199.42,541.35 1188.91,551.86 1188.91,976.84 1275.42,1063.35 1275.42,1283.35 1294.42,1302.35 1294.42,1347.35 1337.42,1390.35 1366.42,1390.35 1379.42,1403.35 1379.42,1609.35 1324.8,1663.97 v1(1321.65,1663.97) ; v1(1656.65,1550.86) 1759.14,1653.35 1895.8,1653.35 1906.42,1663.97 v1(1960.15,1663.97) 2104.8,1663.97 2217.91,1550.86 v1(2263.66,1550.86)
  ART06 w4.1: v1(683.14,1663.97) 807.54,1663.97 914.92,1771.35 939.92,1771.35 955.92,1755.35 1090.42,1755.35 1181.8,1663.97 v1(1321.65,1663.97) 1502.04,1663.97 1609.42,1771.35 1634.42,1771.35 1650.42,1755.35 1747.42,1755.35 1838.8,1663.97 v1(1960.15,1663.97)
DRAM_A4: U1.W14 U2.P8 U3.P8 U4.P8 U5.P8 | length 4641.4
  TOP w6: U5.P8@293.91,1582.36 309.9,1598.35 341.4,1598.35 v1(372.65,1629.6) ; U4.P8@851.89,1582.36 867.88,1598.35 899.38,1598.35 v1(930.63,1629.6) ; v1(1204.65,624.63) U1.W14@1220.4,608.88 ; U3.P8@1546.41,1582.36 1562.4,1598.35 1593.9,1598.35 v1(1625.15,1629.6) ; U2.P8@2153.42,1582.36 2169.41,1598.35 2200.91,1598.35 v1(2232.16,1629.6)
  ART03 w6: v1(372.65,1629.6) 416.67,1629.6 502.42,1715.35 624.28,1715.35 v1(651.64,1742.71) 714.06,1742.71 762.42,1694.35 846.42,1694.35 911.17,1629.6 v1(930.63,1629.6) ; v1(1625.15,1629.6) 1687.67,1629.6 1800.78,1742.71 v1(1928.65,1742.71) 2103.06,1742.71 2216.17,1629.6 v1(2232.16,1629.6)
  ART06 w4.1: v1(651.64,1742.71) 760.78,1742.71 859.11,1841.04 1121.22,1841.04 1219.55,1742.71 v1(1290.15,1742.71) 1439.78,1742.71 1538.11,1841.04 1759.73,1841.04 1858.06,1742.71 v1(1928.65,1742.71)
  BOTTOM w6: v1(1204.65,624.63) 1188.91,640.37 1188.91,775.35 1183.91,780.35 1177.31,780.35 1172.31,785.35 1172.31,795.35 1177.31,800.35 1183.91,800.35 1188.91,805.35 1188.91,833.86 1178.42,844.35 1106.42,844.35 1081.42,819.35 1069.42,819.35 1058.42,830.35 1058.42,886.35 1082.42,910.35 1082.42,1034.35 1178.42,1130.35 1178.42,1696.35 1224.78,1742.71 v1(1290.15,1742.71)
DRAM_A5: U1.AE13 U2.P2 U3.P2 U4.P2 U5.P2 | length 4684.8
  TOP w6: v1(404.15,1613.85) 422.42,1595.58 422.42,1585.35 440.42,1567.35 467.88,1567.35 U5.P2@482.89,1582.36 ; v1(962.13,1613.85) 980.4,1595.58 980.4,1582.35 995.4,1567.35 1025.86,1567.35 U4.P2@1040.87,1582.36 ; v1(1236.15,813.6) U1.AE13@1251.9,797.85 ; v1(1656.65,1613.85) 1674.92,1595.58 1674.92,1582.35 1689.92,1567.35 1720.38,1567.35 U3.P2@1735.39,1582.36 ; v1(2263.66,1613.85) 2281.93,1595.58 2281.93,1582.35 2296.93,1567.35 2327.39,1567.35 U2.P2@2342.4,1582.36
  ART04 w6: v1(404.15,1613.85) 517.26,1726.96 v1(683.14,1726.96) 762.81,1726.96 795.42,1694.35 830.89,1694.35 911.39,1613.85 v1(962.13,1613.85) ; v1(1236.15,813.6) 1236.15,917.08 1246.9,927.83 1246.9,934.2 1228.78,952.32 1228.78,958.68 1235.15,965.05 1241.51,965.05 1259.63,946.92 1265.99,946.92 1272.36,953.29 1272.36,959.65 1254.24,977.77 1254.24,984.14 1260.6,990.5 1266.96,990.5 1285.09,972.38 1291.45,972.38 1297.81,978.74 1297.81,985.11 1279.69,1003.23 1279.69,1009.59 1286.06,1015.96 1292.42,1015.96 1310.54,997.84 1316.91,997.84 1323.27,1004.2 1323.27,1010.56 1305.15,1028.69 1305.15,1035.05 1311.51,1041.41 1317.88,1041.41 1336,1023.29 1342.36,1023.29 1362.42,1043.35 1362.42,1054.35 1350.42,1066.35 1350.42,1287.65 1417.42,1354.65 1417.42,1631.19 1407.53,1641.09 1407.53,1647.45 1420.42,1660.34 1420.42,1666.71 1414.06,1673.07 1407.69,1673.07 1394.8,1660.18 1388.43,1660.18 1382.07,1666.54 1382.07,1672.9 1397.56,1688.39 1397.56,1694.76 1391.19,1701.12 1384.83,1701.12 1369.34,1685.63 1362.98,1685.63 1356.61,1692 1356.61,1698.36 1372.1,1713.85 1372.1,1720.21 1365.74,1726.58 1359.37,1726.58 1343.89,1711.09 1337.52,1711.09 v1(1321.65,1726.96) ; v1(1656.65,1613.85) 1769.76,1726.96 v1(1960.15,1726.96) 2099.81,1726.96 2212.92,1613.85 v1(2263.66,1613.85)
  ART06 w4.1: v1(683.14,1726.96) 767.03,1726.96 868.19,1828.12 1112.14,1828.12 1213.3,1726.96 v1(1321.65,1726.96) 1446.03,1726.96 1547.19,1828.12 1750.65,1828.12 1851.81,1726.96 v1(1960.15,1726.96)
DRAM_A6: U1.AC13 U2.R8 U3.R8 U4.R8 U5.R8 | length 4761.9
  TOP w6: U5.R8@293.91,1613.85 309.42,1629.36 309.42,1661.35 ; 309.91,1661.35 v1(372.65,1724.09) ; U4.R8@851.89,1613.85 867.4,1629.36 867.4,1661.35 867.89,1661.35 v1(930.63,1724.09) ; v1(1236.15,750.61) U1.AC13@1251.9,734.86 ; U3.R8@1546.41,1613.85 1561.92,1629.36 1561.92,1661.35 1562.41,1661.35 v1(1625.15,1724.09) ; U2.R8@2153.42,1613.85 2168.93,1629.36 2168.93,1661.35 2169.42,1661.35 v1(2232.16,1724.09)
  ART03 w6: v1(372.65,1724.09) 424.16,1724.09 474.54,1774.47 588.91,1774.47 v1(651.64,1837.2) 719.57,1837.2 772.42,1784.35 854.89,1784.35 915.15,1724.09 v1(930.63,1724.09) ; v1(1236.15,750.61) 1215.42,771.34 1215.42,848.35 1241.42,874.35 1241.42,1301.35 1180.42,1362.35 1180.42,1690.35 1185.42,1695.35 1209.69,1695.35 1214.69,1700.35 1214.69,1710.35 1209.69,1715.35 1185.42,1715.35 1180.42,1720.35 1180.42,1730.35 1185.42,1735.35 1209.69,1735.35 1214.69,1740.35 1214.69,1750.35 1209.69,1755.35 1185.42,1755.35 1180.42,1760.35 1180.42,1770.35 1185.42,1775.35 1209.69,1775.35 1214.69,1780.35 1214.69,1790.35 1209.69,1795.35 1185.42,1795.35 1180.42,1800.35 1180.42,1823.35 1194.27,1837.2 v1(1290.15,1837.2) ; v1(1625.15,1724.09) 1680.16,1724.09 1793.27,1837.2 v1(1928.65,1837.2) 2103.57,1837.2 2216.68,1724.09 v1(2232.16,1724.09)
  ART06 w4.1: v1(651.64,1837.2) 718.27,1837.2 799.65,1918.58 1171.68,1918.58 1253.06,1837.2 v1(1290.15,1837.2) 1397.27,1837.2 1478.65,1918.58 1810.19,1918.58 1891.57,1837.2 v1(1928.65,1837.2)
DRAM_A7: U1.Y13 U2.R2 U3.R2 U4.R2 U5.R2 | length 4814.2
  TOP w6: v1(404.15,1739.83) 467.42,1676.56 467.42,1629.32 U5.R2@482.89,1613.85 ; v1(962.13,1739.83) 1025.4,1676.56 1025.4,1629.32 U4.R2@1040.87,1613.85 ; U1.Y13@1251.9,640.37 v1(1267.65,624.62) ; v1(1656.65,1739.83) 1719.92,1676.56 1719.92,1629.32 U3.R2@1735.39,1613.85 ; v1(2263.66,1739.83) 2326.93,1676.56 2326.93,1629.32 U2.R2@2342.4,1613.85
  ART04 w6: v1(404.15,1739.83) 517.26,1852.94 v1(683.14,1852.94) 809.3,1852.94 922.41,1739.83 v1(962.13,1739.83) ; v1@1267.65,624.62 1283.4,640.37 1309.44,640.37 1314.89,645.82 1314.89,686.35 1314.89,785.35 1320.42,790.88 1320.42,818.82 1314.89,824.35 1314.89,854.82 1425.42,965.35 1425.42,1210.35 1475.42,1260.35 1475.42,1699.17 v1(1321.65,1852.94) ; v1(1656.65,1739.83) 1769.76,1852.94 v1(1960.15,1852.94) 2110.83,1852.94 2223.94,1739.83 v1(2263.66,1739.83)
  ART06 w4.1: v1(683.14,1852.94) 714.01,1852.94 792.57,1931.5 1184.76,1931.5 1263.32,1852.94 v1(1321.65,1852.94) 1393.01,1852.94 1471.57,1931.5 1823.27,1931.5 1901.83,1852.94 v1(1960.15,1852.94)
DRAM_A8: U1.AB13 U2.T8 U3.T8 U4.T8 U5.T8 | length 4756.4
  TOP w6: U5.T8@293.91,1645.35 293.91,1676.85 v1(372.65,1755.59) ; U4.T8@851.89,1645.35 851.89,1676.85 v1(930.63,1755.59) ; v1(1236.15,719.11) U1.AB13@1251.9,703.36 ; U3.T8@1546.41,1645.35 1546.41,1676.85 v1(1625.15,1755.59) ; U2.T8@2153.42,1645.35 2153.42,1676.85 v1(2232.16,1755.59)
  ART03 w6: v1(372.65,1755.59) 424.66,1755.59 470.99,1801.92 584.85,1801.92 v1(651.64,1868.7) 722.07,1868.7 777.42,1813.35 872.87,1813.35 v1(930.63,1755.59) ; v1(1236.15,719.11) 1214.4,697.35 1199.42,697.35 1188.91,707.86 1188.91,864.84 1220.4,896.33 1220.4,1293.37 1159.42,1354.35 1159.42,1828.35 1199.77,1868.7 1227.42,1868.7 1232.42,1873.7 1232.42,1890.03 1237.42,1895.03 1247.42,1895.03 1252.42,1890.03 1252.42,1873.7 1257.42,1868.7 v1(1290.15,1868.7) ; v1(1625.15,1755.59) 1675.66,1755.59 1788.77,1868.7 v1(1928.65,1868.7) 2119.05,1868.7 v1(2232.16,1755.59)
  ART06 w4.1: v1(651.64,1868.7) 706.77,1868.7 782.5,1944.43 1195.84,1944.43 1271.56,1868.7 v1(1290.15,1868.7) 1385.77,1868.7 1461.5,1944.43 1834.34,1944.43 1910.07,1868.7 v1(1928.65,1868.7)
DRAM_A9: U1.AE12 U2.R3 U3.R3 U4.R3 U5.R3 | length 4588.6
  TOP w6: v1(404.15,1676.84) 404.93,1676.84 433.42,1648.35 433.42,1640.35 451.39,1622.38 U5.R3@451.39,1613.85 ; v1(962.13,1676.84) 962.91,1676.84 985.4,1654.35 985.4,1637.82 U4.R3@1009.37,1613.85 U4.R3@1009.37,1620.4 ; U1.AE12@1283.4,797.85 v1(1299.15,813.6) ; v1(1656.65,1676.84) 1657.43,1676.84 1679.92,1654.35 1679.92,1637.82 U3.R3@1703.89,1613.85 U3.R3@1703.89,1619.87 ; v1(2263.66,1676.84) 2264.44,1676.84 2286.93,1654.35 2286.93,1637.82 U2.R3@2310.9,1613.85 U2.R3@2310.9,1619.87
  ART04 w6: v1(404.15,1676.84) 517.26,1789.95 v1(683.14,1789.95) 809.29,1789.95 922.4,1676.84 v1(962.13,1676.84) ; v1(1299.15,813.6) 1299.15,801.08 1296.42,798.35 1283.42,798.35 1276.42,805.35 1276.42,843.35 1294.66,861.59 1294.66,867.96 1278.4,884.22 1278.4,890.58 1284.76,896.95 1291.13,896.95 1307.39,880.69 1313.76,880.69 1320.12,887.05 1320.12,893.41 1303.86,909.68 1303.86,916.04 1310.22,922.4 1316.58,922.4 1332.85,906.14 1339.21,906.14 1345.58,912.51 1345.58,918.87 1329.31,935.13 1329.31,941.5 1335.68,947.86 1342.04,947.86 1358.3,931.6 1364.67,931.6 1371.03,937.96 1371.03,944.33 1354.77,960.59 1354.77,966.95 1361.13,973.32 1367.5,973.32 1383.76,957.05 1390.12,957.05 1407.42,974.35 1407.42,991.85 1402.92,996.35 1391.02,996.35 1386.52,1000.85 1386.52,1009.85 1391.02,1014.35 1402.92,1014.35 1407.42,1018.85 1407.42,1157.35 1387.42,1177.35 1387.42,1226.35 1457.42,1296.35 1457.42,1689.35 1356.82,1789.95 v1(1321.65,1789.95) ; v1(1656.65,1676.84) 1769.76,1789.95 v1(1960.15,1789.95) 2110.82,1789.95 2223.93,1676.84 v1(2263.66,1676.84)
  ART06 w4.1: v1(683.14,1789.95) 736.77,1789.95 826.63,1879.81 1143.45,1879.81 1233.31,1789.95 v1(1321.65,1789.95) 1415.77,1789.95 1505.63,1879.81 1781.96,1879.81 1871.82,1789.95 v1(1960.15,1789.95)
DRAM_A10: U1.AA15 U2.L7 U3.L7 U4.L7 U5.L7 | length 4453.8
  TOP w6: U5.L7@325.41,1487.87 356.9,1487.87 v1(372.65,1472.12) ; U4.L7@883.39,1487.87 914.88,1487.87 v1(930.63,1472.12) ; v1(1173.16,656.12) U1.AA15@1188.91,671.87 ; U3.L7@1577.91,1487.87 1609.4,1487.87 v1(1625.15,1472.12) ; U2.L7@2184.92,1487.87 2216.41,1487.87 v1(2232.16,1472.12)
  ART03 w6: v1(372.65,1472.12) 425.19,1472.12 467.42,1514.35 542.42,1514.35 613.3,1585.23 v1(651.64,1585.23) 696.01,1585.23 768.89,1512.35 890.4,1512.35 v1(930.63,1472.12) ; v1(1625.15,1472.12) 1676.19,1472.12 1700.42,1496.35 1813.42,1496.35 1902.3,1585.23 v1(1928.65,1585.23) 1997.54,1585.23 2066.42,1516.35 2187.93,1516.35 v1(2232.16,1472.12)
  ART04 w6: v1(1173.16,656.12) 1157.41,640.37 944.4,640.37 900.42,684.35 900.42,806.35 858.42,848.35 858.42,1077.35 916.42,1135.35 1091.42,1135.35 1111.42,1155.35 1111.42,1340.35 1139.42,1368.35 1139.42,1501.35 1228.42,1590.35 1285.03,1590.35 v1(1290.15,1585.23)
  ART06 w4.1: v1(651.64,1585.23) 867.92,1585.23 896.04,1613.35 937.92,1613.35 952.92,1598.35 991.92,1598.35 1005.04,1585.23 v1(1290.15,1585.23) 1562.42,1585.23 1590.54,1613.35 1632.42,1613.35 1647.42,1598.35 1686.42,1598.35 1699.54,1585.23 v1(1928.65,1585.23)
DRAM_A11: U1.AC12 U2.R7 U3.R7 U4.R7 U5.R7 | length 4543.1
  TOP w6: U5.R7@325.41,1613.85 325.41,1614.34 372.16,1661.09 v1(372.65,1661.1) ; v1(930.63,1661.1) 930.14,1661.09 U4.R7@883.39,1614.34 ; U1.AC12@1283.4,734.86 v1(1299.15,750.61) ; v1(1625.15,1661.1) 1624.66,1661.09 U3.R7@1577.91,1614.34 ; v1(2232.16,1661.1) 2231.67,1661.09 U2.R7@2184.92,1614.34 ; U4.R7@883.39,1614.34 U4.R7@883.39,1613.85 U4.R7@883.39,1614.34 ; U3.R7@1577.91,1614.34 U3.R7@1577.91,1613.85 U3.R7@1577.91,1614.34 ; U2.R7@2184.92,1614.34 U2.R7@2184.92,1613.85 U2.R7@2184.92,1614.34
  ART03 w6: v1(372.65,1661.1) 422.17,1661.1 494.42,1733.35 610.78,1733.35 v1(651.64,1774.21) 724.56,1774.21 756.42,1742.35 829.89,1742.35 911.14,1661.1 v1(930.63,1661.1) ; v1(1290.15,1774.21) 1256.42,1740.48 1256.42,1478.35 1251.42,1473.35 1225.42,1473.35 1220.42,1468.35 1220.42,1458.35 1225.42,1453.35 1251.42,1453.35 1256.42,1448.35 1256.42,1438.35 1251.42,1433.35 1225.42,1433.35 1220.42,1428.35 1220.42,1418.35 1225.42,1413.35 1251.42,1413.35 1256.42,1408.35 1256.42,1398.35 1251.42,1393.35 1225.42,1393.35 1220.42,1388.35 1220.42,1378.35 1238.93,1359.84 1246,1359.84 1256.8,1370.65 1263.88,1370.65 1270.95,1363.58 1270.95,1356.51 1260.14,1345.7 1260.14,1338.63 1267.21,1331.56 1274.28,1331.56 1285.09,1342.37 1292.16,1342.37 1299.23,1335.3 1299.23,1328.23 1288.42,1317.42 1288.42,1310.35 1301.42,1297.35 1332.42,1297.35 1337.42,1292.35 1337.42,1282.35 1332.42,1277.35 1294.42,1277.35 1289.42,1272.35 1289.42,1262.35 1294.42,1257.35 1332.42,1257.35 1337.42,1252.35 1337.42,1242.35 1332.42,1237.35 1294.42,1237.35 1289.42,1232.35 1289.42,832.35 1283.42,826.35 1283.42,766.33 v1(1299.15,750.61) ; v1(1625.15,1661.1) 1687.17,1661.1 1800.28,1774.21 v1(1928.65,1774.21) 2099.56,1774.21 2212.67,1661.1 v1(2232.16,1661.1)
  ART06 w4.1: v1(651.64,1774.21) 749.28,1774.21 841.96,1866.89 1134.37,1866.89 1227.05,1774.21 v1(1290.15,1774.21) 1428.28,1774.21 1520.96,1866.89 1772.88,1866.89 1865.56,1774.21 v1(1928.65,1774.21)
DRAM_A12: U1.AD12 U2.N7 U3.N7 U4.N7 U5.N7 | length 4503.3
  TOP w6: U5.N7@325.41,1550.86 356.91,1550.86 v1(372.65,1535.12) v1@372.42,1535.35 ; U4.N7@883.39,1550.86 914.89,1550.86 v1(930.63,1535.12) ; U1.AD12@1283.4,766.36 v1(1299.15,782.11) ; U3.N7@1577.91,1550.86 1609.41,1550.86 v1(1625.15,1535.12) v1@1624.92,1535.35 ; U2.N7@2184.92,1550.86 2216.42,1550.86 v1(2232.16,1535.12) v1@2231.93,1535.35
  ART03 w6: v1(372.65,1535.12) 418.66,1535.12 517.89,1634.35 637.76,1634.35 v1(651.64,1648.23) 701.42,1648.23 712.3,1637.35 821.42,1637.35 923.65,1535.12 v1(930.63,1535.12) ; v1(1625.15,1535.12) 1720.19,1535.12 1833.3,1648.23 v1(1928.65,1648.23) 2115.54,1648.23 2228.65,1535.12 v1(2232.16,1535.12)
  ART06 w4.1: v1(651.64,1648.23) 818.53,1648.23 910.65,1740.35 937.92,1740.35 953.92,1724.35 1086.91,1724.35 1163.03,1648.23 v1(1290.15,1648.23) 1513.03,1648.23 1605.15,1740.35 1632.42,1740.35 1648.42,1724.35 1725.42,1724.35 1801.54,1648.23 v1(1928.65,1648.23)
  BOTTOM w6: v1(1290.15,1648.23) 1256.3,1648.23 1233.42,1625.35 1233.42,1297.35 1270.42,1260.35 1270.42,1242.35 1275.42,1237.35 1297.97,1237.35 1302.97,1232.35 1302.97,1222.35 1297.97,1217.35 1275.42,1217.35 1270.42,1212.35 1270.42,1189.35 1265.42,1184.35 1238.75,1184.35 1233.75,1179.35 1233.75,1169.35 1238.75,1164.35 1265.42,1164.35 1270.42,1159.35 1270.42,1149.35 1265.42,1144.35 1238.75,1144.35 1233.75,1139.35 1233.75,1129.35 1238.75,1124.35 1265.42,1124.35 1270.42,1119.35 1270.42,1109.35 1265.42,1104.35 1238.75,1104.35 1233.75,1099.35 1233.75,1089.35 1238.75,1084.35 1265.42,1084.35 1270.42,1079.35 1270.42,1069.35 1265.42,1064.35 1238.75,1064.35 1233.75,1059.35 1233.75,1049.35 1238.75,1044.35 1265.42,1044.35 1270.42,1039.35 1270.42,1029.35 1265.42,1024.35 1238.75,1024.35 1233.75,1019.35 1233.75,1009.35 1238.75,1004.35 1265.42,1004.35 1270.42,999.35 1270.42,989.35 1265.42,984.35 1238.75,984.35 1233.75,979.35 1233.75,969.35 1238.75,964.35 1265.42,964.35 1270.42,959.35 1270.42,949.35 1265.42,944.35 1238.75,944.35 1233.75,939.35 1233.75,929.35 1238.75,924.35 1265.42,924.35 1270.42,919.35 1270.42,909.35 1265.42,904.35 1238.75,904.35 1233.75,899.35 1233.75,889.35 1238.75,884.35 1265.42,884.35 1270.42,879.35 1270.42,859.35 1283.42,846.35 1283.42,797.83 v1(1299.15,782.11)
DRAM_A13: U1.AC17 U2.T3 U3.T3 U4.T3 U5.T3 | length 4582.5
  TOP w6: v1(404.15,1708.33) 451.39,1661.09 U5.T3@451.39,1645.35 ; v1(962.13,1708.33) 1009.37,1661.09 U4.T3@1009.37,1645.35 ; v1(1110.17,750.61) U1.AC17@1125.92,734.86 ; v1(1656.65,1708.33) 1703.89,1661.09 U3.T3@1703.89,1645.35 ; v1(2263.66,1708.33) 2310.9,1661.09 U2.T3@2310.9,1645.35
  ART04 w6: v1(404.15,1708.33) 517.26,1821.44 v1(683.14,1821.44) 805.8,1821.44 918.91,1708.33 v1(962.13,1708.33) ; v1(1656.65,1708.33) 1769.76,1821.44 v1(1960.15,1821.44) 2107.33,1821.44 2220.44,1708.33 v1(2263.66,1708.33)
  ART06 w4.1: v1(683.14,1821.44) 723.51,1821.44 807.73,1905.66 1158.61,1905.66 1242.82,1821.44 v1(1321.65,1821.44) 1402.51,1821.44 1486.73,1905.66 1797.11,1905.66 1881.33,1821.44 v1(1960.15,1821.44)
  BOTTOM w6: v1(1110.17,750.61) 1036.42,824.36 1036.42,893.35 1063.42,920.35 1063.42,1049.35 1159.42,1145.35 1159.42,1162.35 1154.42,1167.35 1124.42,1167.35 1119.42,1172.35 1119.42,1182.35 1124.42,1187.35 1154.42,1187.35 1159.42,1192.35 1159.42,1800.35 1180.51,1821.44 1214.42,1821.44 1219.42,1826.44 1219.42,1843.48 1224.42,1848.48 1234.42,1848.48 1239.42,1843.48 1239.42,1799.41 1244.42,1794.41 1254.42,1794.41 1259.42,1799.41 1259.42,1816.44 1264.42,1821.44 v1(1321.65,1821.44)
DRAM_A14: U1.AA12 U2.T7 U3.T7 U4.T7 U5.T7 | length 4534.3
  TOP w6: U5.T7@325.41,1645.35 v1@372.41,1692.35 ; U4.T7@883.39,1645.35 v1@930.63,1692.59 ; U1.AA12@1283.4,671.87 v1(1299.15,687.62) ; U3.T7@1577.91,1645.35 v1@1625.15,1692.59 ; U2.T7@2184.92,1645.35 v1@2232.16,1692.59
  ART03 w6: v1(372.16,1692.59) 423.66,1692.59 485.42,1754.35 599.8,1754.35 v1(651.15,1805.7) 721.07,1805.7 762.42,1764.35 839.89,1764.35 911.65,1692.59 v1(930.14,1692.59) ; v1(1289.66,1805.7) 1279.01,1816.35 1248.42,1816.35 1235.42,1803.35 1235.42,1693.35 1201.42,1659.35 1201.42,1643.35 1206.42,1638.35 1228.19,1638.35 1233.19,1633.35 1233.19,1623.35 1228.19,1618.35 1206.42,1618.35 1201.42,1613.35 1201.42,1603.35 1206.42,1598.35 1228.19,1598.35 1233.19,1593.35 1233.19,1583.35 1228.19,1578.35 1206.42,1578.35 1201.42,1573.35 1201.42,1563.35 1206.42,1558.35 1228.19,1558.35 1233.19,1553.35 1233.19,1543.35 1228.19,1538.35 1206.42,1538.35 1201.42,1533.35 1201.42,1523.35 1206.42,1518.35 1228.19,1518.35 1233.19,1513.35 1233.19,1503.35 1228.19,1498.35 1206.42,1498.35 1201.42,1493.35 1201.42,1369.35 1267.42,1303.35 1267.42,854.35 1255.42,842.35 1255.42,697.35 1265.15,687.62 v1(1299.15,687.62) ; v1(1624.66,1692.59) 1685.66,1692.59 1798.77,1805.7 v1(1928.17,1805.7) 2100.07,1805.7 2213.18,1692.59 v1(2231.67,1692.59)
  ART06 w4.1: v1(651.15,1805.7) 730.77,1805.7 817.8,1892.73 1152.53,1892.73 1239.56,1805.7 v1(1289.66,1805.7) 1409.77,1805.7 1496.8,1892.73 1791.04,1892.73 1878.07,1805.7 v1(1928.17,1805.7)
DRAM_A15: U1.Y12 U2.M7 U3.M7 U4.M7 U5.M7 | length 4479.4
  TOP w6: U5.M7@325.41,1519.37 356.9,1519.37 v1(372.65,1503.62) ; U4.M7@883.39,1519.37 914.88,1519.37 v1(930.63,1503.62) ; U1.Y12@1283.4,640.37 v1(1299.15,656.12) ; U3.M7@1577.91,1519.37 1609.4,1519.37 v1(1625.15,1503.62) ; U2.M7@2184.92,1519.37 2216.41,1519.37 v1(2232.16,1503.62)
  ART03 w6: v1(372.65,1503.62) 424.69,1503.62 527.42,1606.35 641.26,1606.35 v1(651.64,1616.73) 814.04,1616.73 927.15,1503.62 v1(930.63,1503.62) ; v1(1625.15,1503.62) 1674.69,1503.62 1687.93,1516.86 1787.93,1516.86 1887.8,1616.73 v1(1928.65,1616.73) 2119.05,1616.73 v1(2232.16,1503.62)
  ART06 w4.1: v1(651.64,1616.73) 854.92,1616.73 915.54,1677.35 938.92,1677.35 955.92,1660.35 1006.42,1660.35 1050.04,1616.73 v1(1290.15,1616.73) 1549.42,1616.73 1610.04,1677.35 1633.42,1677.35 1650.42,1660.35 1696.42,1660.35 1740.04,1616.73 v1(1928.65,1616.73)
  BOTTOM w6: v1(1290.15,1616.73) 1271.42,1598 1271.42,1418.35 1287.42,1402.35 1287.42,1308.35 1346.42,1249.35 1346.42,1223.35 1351.42,1218.35 1382.97,1218.35 1387.97,1213.35 1387.97,1203.35 1382.97,1198.35 1351.42,1198.35 1346.42,1193.35 1346.42,1174.35 1355.42,1165.35 1397.08,1165.35 1402.08,1160.35 1402.08,1150.35 1397.08,1145.35 1355.42,1145.35 1346.42,1136.35 1346.42,1113.35 1351.42,1108.35 1397.42,1108.35 1402.42,1103.35 1402.42,1093.35 1397.42,1088.35 1351.42,1088.35 1346.42,1083.35 1346.42,1073.35 1351.42,1068.35 1397.42,1068.35 1402.42,1063.35 1402.42,1053.35 1397.42,1048.35 1351.42,1048.35 1346.42,1043.35 1346.42,1033.35 1351.42,1028.35 1397.42,1028.35 1402.42,1023.35 1402.42,1009.35 1381.04,987.97 1373.97,987.97 1361.24,1000.7 1354.17,1000.7 1347.1,993.63 1347.1,986.55 1359.83,973.83 1359.83,966.76 1346.39,953.32 1346.39,712.33 1337.42,703.36 1322.43,703.36 1314.89,695.82 1314.89,671.86 v1(1299.15,656.12)
DRAM_CAS_B: U1.AE16 U2.K3 U3.K3 U4.K3 U5.K3 | length 4491.2
  TOP w6: v1(404.15,1424.86) 419.89,1424.87 U5.K3@451.39,1456.37 ; v1(962.13,1424.86) 977.87,1424.87 U4.K3@1009.37,1456.37 ; v1(1141.66,813.6) U1.AE16@1157.41,797.85 ; v1(1656.65,1424.86) 1672.39,1424.87 U3.K3@1703.89,1456.37 ; v1(2263.66,1424.86) 2279.4,1424.87 U2.K3@2310.9,1456.37
  ART04 w6: v1(404.15,1424.86) 491.64,1512.35 551.89,1512.35 577.51,1537.97 v1(683.14,1537.97) 692.27,1537.97 757.89,1472.35 860.4,1472.35 907.89,1424.86 v1(962.13,1424.86) ; v1(1141.66,813.6) 1128.42,800.35 1093.42,800.35 1081.42,812.35 1081.42,825.2 1076.92,829.7 1067.92,829.7 1063.42,825.2 1063.42,804.85 1058.92,800.35 1044.42,800.35 1038.42,806.35 1038.42,843.35 1045.42,850.35 1057.42,850.35 1062.42,855.35 1062.42,864.35 1057.42,869.35 1042.42,869.35 1038.42,873.35 1038.42,888.35 1045.42,895.35 1057.42,895.35 1062.42,900.35 1062.42,909.35 1057.42,914.35 1042.42,914.35 1038.42,918.35 1038.42,927.35 1052.42,941.35 1079.42,941.35 1084.42,936.35 1084.42,902.35 1101.42,885.35 1101.42,853.35 1107.42,847.35 1133.42,847.35 1141.66,855.59 1141.66,964.85 1137.16,969.35 1090.16,969.35 1085.66,973.85 1085.66,982.85 1090.16,987.35 1137.16,987.35 1141.66,991.85 1141.66,1000.85 1137.16,1005.35 1090.16,1005.35 1085.66,1009.85 1085.66,1018.85 1090.16,1023.35 1137.16,1023.35 1141.66,1027.85 1141.66,1044.59 1206.42,1109.35 1206.42,1276.35 1253.42,1323.35 1253.42,1361.35 1340.42,1448.35 1340.42,1519.2 v1(1321.65,1537.97) ; v1(1656.65,1424.86) 1744.14,1512.35 1853.42,1512.35 1879.04,1537.97 v1(1960.15,1537.97) 1993.8,1537.97 2059.42,1472.35 2161.93,1472.35 2209.42,1424.86 v1(2263.66,1424.86)
  ART06 w4.1: v1(683.14,1537.97) 749.8,1537.97 786.42,1501.35 896.92,1501.35 914.92,1519.35 937.92,1519.35 952.92,1504.35 1191.91,1504.35 1225.54,1537.97 v1(1321.65,1537.97) 1437.42,1537.97 1474.04,1501.35 1591.42,1501.35 1609.42,1519.35 1632.42,1519.35 1647.42,1504.35 1830.42,1504.35 1864.04,1537.97 v1(1960.15,1537.97)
